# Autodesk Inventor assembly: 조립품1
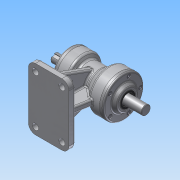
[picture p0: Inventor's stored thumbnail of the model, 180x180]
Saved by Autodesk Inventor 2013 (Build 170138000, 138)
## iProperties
Created: 2015-08
Part Number: 조립품1
Document SubType Name: Assembly
Designer: User11
Author: User11
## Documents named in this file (10)
- C:\Users\User11\Desktop\450805V1018zip\조립품1.iam
- C:\Users\User11\Desktop\450805V1018zip\본체.ipt
- C:\Users\User11\Desktop\450805V1018zip\450805V1018 (2)\M4x0.5.ipt
- C:\Users\User11\Desktop\450805V1018zip\450805V1018 (2)\뒤커버.ipt
- C:\Users\User11\Desktop\450805V1018zip\450805V1018 (2)\베어링 6203.ipt
- C:\Users\User11\Desktop\450805V1018zip\450805V1018 (2)\베어링 6205.ipt
- C:\Users\User11\Desktop\450805V1018zip\450805V1018 (2)\앞커버.ipt
- C:\Users\User11\Desktop\450805V1018zip\450805V1018 (2)\오일실 .ipt
- 오일실 .ipt
- C:\Users\User11\Desktop\450805V1018zip\450805V1018 (2)\축.ipt
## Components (11 placed, 1 different names)
1. M4x0.5:1
2. M4x0.5:2
3. M4x0.5:3
4. M4x0.5:4
5. M4x0.5:5
6. M4x0.5:6
7. M4x0.5:7
8. M4x0.5:8
9. M4x0.5:9
10. M4x0.5:10
11. M4x0.5:11
